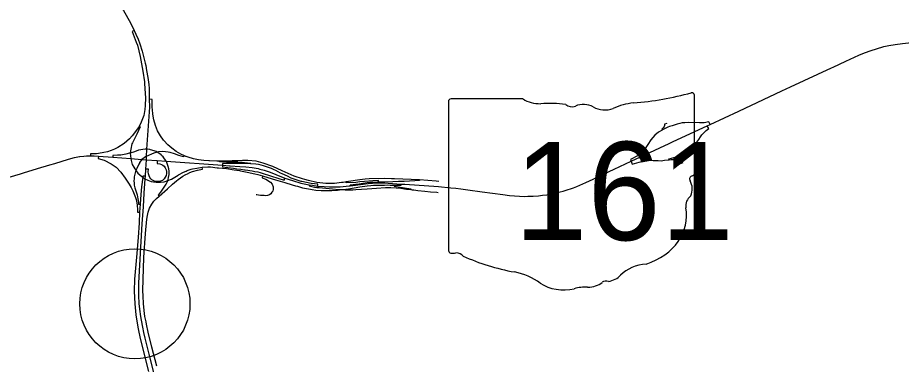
# Model space of a CAD drawing. Extents: x 0 to 34, y 0 to 22.
# Drawn here: x 6.732 to 7.89, y 18.908 to 19.363 of the extents above; entities that cross this region are included whole.
import ezdxf

# ---------------------------------------------------------------- set-up
doc = ezdxf.new("R2010")
doc.units = 0
for name, color, linetype in [('GM_X_Interchange_Ramps', 7, 'Continuous'), ('GM_X_Interstate_Route', 7, 'Continuous'), ('GM_X_State_Route', 7, 'Continuous'), ('GM_X_State_Shield', 7, 'Continuous'), ('SH_Text', 7, 'Continuous')]:
    doc.layers.add(name, color=color, linetype=linetype)

msp = doc.modelspace()

# ---------------------------------------------------------------- linework, layer by layer
at = {"layer": 'GM_X_Interchange_Ramps'}
for points in [[(6.8844, 19.3456), (6.8816, 19.3444), (6.887, 19.3303), (6.8885, 19.3264), (6.8924, 19.3115), (6.8959, 19.2923), (6.8977, 19.2784), (6.8979, 19.2767), (6.8985, 19.269), (6.899, 19.2572), (6.8986, 19.2475), (6.8983, 19.2419), (6.897, 19.2343), (6.8963, 19.2319), (6.8937, 19.2253), (6.8909, 19.22), (6.8876, 19.2152), (6.8818, 19.2074), (6.8784, 19.2038), (6.8747, 19.2005), (6.8711, 19.1977), (6.8629, 19.1921), (6.8585, 19.1901), (6.854, 19.1882), (6.8493, 19.1867), (6.8446, 19.1856), (6.8423, 19.1851), (6.835, 19.1841), (6.8273, 19.1839), (6.8273, 19.1815)], [(7.2835, 19.1476), (7.2801, 19.148), (7.2582, 19.15), (7.2255, 19.151), (7.2215, 19.1511), (7.2119, 19.1515), (7.1923, 19.1511), (7.187, 19.1506), (7.1801, 19.1499), (7.1651, 19.1477), (7.162, 19.1472), (7.1584, 19.1466), (7.1562, 19.1462), (7.1468, 19.1452), (7.1354, 19.1452), (7.1238, 19.1466), (7.1129, 19.1489), (7.1079, 19.1503), (7.1049, 19.1512), (7.0942, 19.1547), (7.0783, 19.1617), (7.066, 19.1673), (7.0536, 19.1718), (7.0474, 19.1734), (7.0441, 19.1742), (7.0335, 19.1751), (7.03, 19.1752), (7.0265, 19.1752), (7.0203, 19.1748), (7.0129, 19.1747), (7.0028, 19.1744), (6.9983, 19.1744), (6.9962, 19.1744), (6.9927, 19.1745), (6.983, 19.175), (6.9824, 19.175), (6.9756, 19.1754), (6.9688, 19.1762), (6.9621, 19.1774), (6.9553, 19.1794), (6.9525, 19.1804), (6.9519, 19.1806), (6.9496, 19.1817), (6.9455, 19.1835), (6.9424, 19.1852), (6.9394, 19.187), (6.9336, 19.1912), (6.9283, 19.1959), (6.9233, 19.2014), (6.9229, 19.2019), (6.9189, 19.2075), (6.9151, 19.2142), (6.9121, 19.2212), (6.91, 19.2284), (6.9088, 19.2358), (6.9087, 19.237), (6.9078, 19.2454), (6.9081, 19.2554), (6.9042, 19.2555)], [(7.5823, 19.2239), (7.5795, 19.2227), (7.5792, 19.2213), (7.5787, 19.2198), (7.578, 19.2185), (7.5769, 19.2171), (7.5759, 19.2161), (7.5764, 19.2151)], [(7.639, 19.2225), (7.6373, 19.2258), (7.6312, 19.2247), (7.6252, 19.2244), (7.6102, 19.2249), (7.6059, 19.2248), (7.6024, 19.2244), (7.5994, 19.2238), (7.5958, 19.2229), (7.5896, 19.2208), (7.5861, 19.2198), (7.5837, 19.2188)], [(6.8909, 19.22), (6.8924, 19.2195), (6.8879, 19.2099), (6.8823, 19.1986), (6.8815, 19.1969), (6.8798, 19.1902), (6.8794, 19.1877), (6.879, 19.185), (6.8798, 19.1779), (6.8803, 19.1754), (6.8819, 19.1701), (6.8839, 19.1664), (6.8851, 19.1642), (6.8864, 19.1625), (6.8871, 19.1615), (6.8892, 19.1588), (6.8942, 19.1542), (6.8955, 19.1534), (6.8984, 19.1514), (6.9022, 19.1494), (6.9068, 19.1478), (6.9098, 19.1474), (6.9132, 19.1469), (6.9167, 19.1468), (6.9188, 19.147), (6.9236, 19.1474), (6.9283, 19.1488), (6.9333, 19.1508), (6.9419, 19.156), (6.9426, 19.1564), (6.949, 19.1599), (6.9523, 19.1614), (6.954, 19.162), (6.9592, 19.1639), (6.9607, 19.1642), (6.9663, 19.1653), (6.9735, 19.1666), (6.9807, 19.1669), (6.9842, 19.1668), (6.9931, 19.1658), (6.9947, 19.1656), (7.0053, 19.1646), (7.0156, 19.1632), (7.0223, 19.1621), (7.0237, 19.1618), (7.0323, 19.1601), (7.0423, 19.1578), (7.0462, 19.1568), (7.0524, 19.1551), (7.0652, 19.1513), (7.0695, 19.15), (7.0816, 19.1463), (7.0915, 19.1433), (7.0956, 19.1421), (7.0983, 19.1414), (7.1051, 19.1396), (7.1154, 19.1375), (7.1177, 19.1372), (7.1224, 19.1365), (7.1293, 19.1359), (7.1304, 19.1359), (7.1364, 19.1357), (7.1417, 19.1358), (7.1435, 19.1358), (7.1507, 19.1363), (7.1561, 19.137), (7.158, 19.1373), (7.1652, 19.1382), (7.1726, 19.1395), (7.1801, 19.1407), (7.1895, 19.1419), (7.1946, 19.1425), (7.1982, 19.1428), (7.2018, 19.1429), (7.2054, 19.1431), (7.2105, 19.1431), (7.2126, 19.1431), (7.2162, 19.1432), (7.2197, 19.1431), (7.2249, 19.143), (7.227, 19.143), (7.2306, 19.1429), (7.2342, 19.1427), (7.2344, 19.1444)], [(7.5837, 19.2188), (7.582, 19.2181), (7.5775, 19.2157), (7.5764, 19.2151), (7.5717, 19.2123), (7.5666, 19.2085), (7.5616, 19.2024), (7.5576, 19.1961), (7.5541, 19.1909), (7.5503, 19.1864), (7.5447, 19.1818), (7.5346, 19.1765), (7.5356, 19.1742)], [(7.5994, 19.1816), (7.6029, 19.1825), (7.6076, 19.1856), (7.6121, 19.1884), (7.6165, 19.1919), (7.6191, 19.1951), (7.6219, 19.1993), (7.6243, 19.2029), (7.6264, 19.2062), (7.6282, 19.2089), (7.631, 19.2117), (7.6339, 19.2145), (7.6373, 19.2172), (7.6354, 19.2208)], [(6.917, 19.1285), (6.916, 19.1297), (6.9172, 19.1312), (6.9191, 19.1338), (6.921, 19.1364), (6.9228, 19.139), (6.9246, 19.1416), (6.9262, 19.1442), (6.9275, 19.1469), (6.9283, 19.1488), (6.9292, 19.1525), (6.9299, 19.1554), (6.93, 19.1564), (6.9301, 19.1584), (6.9301, 19.1613), (6.9297, 19.1643), (6.9291, 19.1672), (6.9282, 19.17), (6.9271, 19.1727), (6.9262, 19.1743), (6.9257, 19.1752), (6.9242, 19.1776), (6.9223, 19.1799), (6.9203, 19.182), (6.9196, 19.1825), (6.918, 19.1839), (6.9145, 19.1862), (6.9131, 19.1869), (6.9104, 19.1881), (6.9058, 19.1893), (6.9048, 19.1896), (6.9018, 19.1899), (6.9007, 19.1899), (6.8989, 19.1899), (6.8959, 19.1897), (6.893, 19.1893), (6.8902, 19.1886), (6.8846, 19.1866), (6.879, 19.185), (6.8781, 19.1847), (6.8734, 19.1835), (6.8668, 19.1824), (6.8623, 19.1821), (6.8566, 19.1819), (6.8565, 19.1796)], [(6.8374, 19.1811), (6.8373, 19.1779), (6.8451, 19.1757), (6.8541, 19.1709), (6.8607, 19.1664), (6.8667, 19.1601), (6.8725, 19.1522), (6.878, 19.1442), (6.8806, 19.1397), (6.8827, 19.1356), (6.8845, 19.1312), (6.886, 19.1268), (6.8869, 19.1243), (6.8872, 19.1219), (6.8881, 19.1173), (6.8884, 19.1147), (6.8885, 19.1123), (6.8887, 19.1075), (6.8915, 19.1075)], [(6.9496, 19.1817), (6.9492, 19.1802), (6.9431, 19.182), (6.9371, 19.1839), (6.9315, 19.1856), (6.9287, 19.1863), (6.9218, 19.1871), (6.9163, 19.1866), (6.9145, 19.1862), (6.9103, 19.185), (6.9069, 19.1837), (6.9032, 19.1819), (6.9002, 19.1806), (6.8994, 19.1802), (6.8973, 19.1786), (6.8945, 19.1764), (6.8915, 19.1724), (6.8912, 19.1719), (6.8905, 19.1703), (6.8895, 19.1681), (6.8873, 19.1643), (6.8867, 19.163), (6.8864, 19.1625), (6.8851, 19.1573), (6.8845, 19.1538), (6.8842, 19.151), (6.884, 19.1487), (6.8842, 19.1455), (6.8844, 19.1427), (6.8853, 19.1394), (6.8881, 19.13), (6.8893, 19.1251), (6.89, 19.1206), (6.8901, 19.1178), (6.8923, 19.1178)], [(7.5855, 19.1763), (7.5852, 19.1773), (7.5886, 19.1781), (7.5979, 19.1811), (7.5994, 19.1816)], [(6.9142, 18.9055), (6.9076, 18.9307), (6.9029, 18.9502), (6.9006, 18.9605), (6.8999, 18.9638), (6.8985, 18.9707), (6.8974, 18.9786), (6.8964, 18.9878), (6.896, 18.9973), (6.8956, 19.0046), (6.8972, 19.0481), (6.8993, 19.0797), (6.9011, 19.0984), (6.9019, 19.1033), (6.9028, 19.1073), (6.9046, 19.1126), (6.9074, 19.1178), (6.9103, 19.1217), (6.9138, 19.1255), (6.917, 19.1285), (6.9281, 19.1382), (6.9348, 19.1441), (6.9397, 19.1485), (6.9419, 19.1502), (6.945, 19.1526), (6.948, 19.1546), (6.951, 19.1563), (6.952, 19.1568), (6.9541, 19.1578), (6.9573, 19.1593), (6.9606, 19.1606), (6.9672, 19.1626), (6.9717, 19.1634), (6.974, 19.1639), (6.9735, 19.1666)], [(6.9147, 19.1752), (6.9145, 19.1714), (6.9178, 19.1707), (6.92, 19.17), (6.9218, 19.169), (6.9236, 19.1676), (6.925, 19.1657), (6.9263, 19.163), (6.9267, 19.1609), (6.9268, 19.1584), (6.9262, 19.1557), (6.9251, 19.1534), (6.9236, 19.1511), (6.9213, 19.1491), (6.9187, 19.148), (6.9171, 19.1476), (6.9146, 19.1475), (6.912, 19.1479), (6.91, 19.1486), (6.9077, 19.15), (6.9063, 19.1514), (6.9049, 19.153), (6.9038, 19.1552), (6.903, 19.1577), (6.9029, 19.1602), (6.9032, 19.1639), (6.8992, 19.164)], [(7.037, 19.1708), (7.0371, 19.1713), (7.0288, 19.1721), (7.0257, 19.1724), (7.0227, 19.1727), (7.0203, 19.1729), (7.0132, 19.1729), (7.0105, 19.173), (7.0079, 19.173), (7.0052, 19.1731), (6.9963, 19.1735), (6.9962, 19.1744)], [(7.0001, 19.169), (7, 19.1669), (7.0036, 19.1665), (7.007, 19.1661), (7.0147, 19.1651), (7.0187, 19.1645), (7.024, 19.1637), (7.029, 19.1631), (7.0299, 19.163), (7.0335, 19.1625), (7.0358, 19.1621), (7.0392, 19.1617), (7.0427, 19.161), (7.0464, 19.1602)], [(7.0472, 19.1701), (7.0439, 19.1703), (7.037, 19.1708), (7.0316, 19.1711), (7.0261, 19.1713), (7.0193, 19.1712), (7.0003, 19.1714), (7.0001, 19.169)], [(7.1246, 19.1417), (7.1249, 19.1441), (7.1164, 19.1452), (7.1042, 19.1475), (7.1031, 19.1477), (7.0952, 19.1502), (7.0901, 19.1522), (7.0851, 19.1545), (7.0785, 19.1577), (7.0761, 19.1588), (7.0699, 19.1621), (7.0677, 19.1631), (7.0642, 19.1646), (7.054, 19.1682), (7.0508, 19.1691), (7.0472, 19.1701)], [(7.5356, 19.1742), (7.5371, 19.1704), (7.546, 19.1731), (7.5535, 19.1748), (7.5591, 19.1757), (7.5647, 19.1752), (7.5711, 19.1751), (7.5752, 19.175), (7.5793, 19.1756), (7.5855, 19.1763), (7.588, 19.1767), (7.5908, 19.1764), (7.5936, 19.1755), (7.5959, 19.1745), (7.5978, 19.1735), (7.5992, 19.1724), (7.6002, 19.1714), (7.6036, 19.1727)], [(6.8986, 19.1546), (6.8957, 19.1549), (6.8955, 19.1534), (6.8938, 19.1409), (6.8931, 19.1308), (6.8923, 19.1178), (6.8915, 19.1075), (6.8907, 19.0934), (6.8895, 19.0743), (6.8873, 19.0485), (6.8859, 19.0339), (6.885, 19.0195), (6.8842, 19.0039), (6.8853, 18.9873), (6.8865, 18.973), (6.8882, 18.962), (6.8898, 18.9544), (6.8923, 18.9419), (6.9032, 18.8985)], [(7.0524, 19.1551), (7.0521, 19.1527), (7.057, 19.1506), (7.0631, 19.1467), (7.0653, 19.1441), (7.0667, 19.1405), (7.0667, 19.1378), (7.0661, 19.1351), (7.0649, 19.1337), (7.0635, 19.1316), (7.0615, 19.1304), (7.0592, 19.1295), (7.057, 19.1291), (7.0547, 19.1292), (7.0522, 19.1293), (7.05, 19.1295), (7.0473, 19.1299), (7.0452, 19.1303), (7.0444, 19.1304)], [(7.0464, 19.1602), (7.0495, 19.1597), (7.0657, 19.1542), (7.0714, 19.1524), (7.0752, 19.1512), (7.0783, 19.1503), (7.081, 19.1495), (7.0817, 19.1522)], [(7.1139, 19.1434), (7.1136, 19.1419), (7.1208, 19.1404), (7.1237, 19.14), (7.1267, 19.1397), (7.1441, 19.138), (7.1527, 19.1372), (7.1561, 19.137), (7.1609, 19.1367), (7.1649, 19.1366), (7.1707, 19.1367), (7.1748, 19.1371), (7.1897, 19.1381), (7.2018, 19.139), (7.2137, 19.1397), (7.2208, 19.1397), (7.2276, 19.1393), (7.2338, 19.1388), (7.2414, 19.1377), (7.2468, 19.1371), (7.2488, 19.1369), (7.2509, 19.1366), (7.2562, 19.136), (7.2652, 19.135), (7.2729, 19.1343), (7.281, 19.1336), (7.2828, 19.1334)], [(7.2042, 19.1458), (7.2042, 19.1468), (7.2044, 19.1492), (7.197, 19.1487), (7.1864, 19.1478), (7.1802, 19.1471), (7.1747, 19.1465), (7.1621, 19.1458), (7.162, 19.1472)], [(7.2582, 19.15), (7.2581, 19.1492), (7.2521, 19.1487), (7.2452, 19.1483), (7.2381, 19.1479), (7.2308, 19.1475), (7.2234, 19.1472), (7.2127, 19.147), (7.2042, 19.1468), (7.1985, 19.1466), (7.1926, 19.1462), (7.1842, 19.1452), (7.179, 19.1444), (7.1747, 19.1437), (7.1676, 19.1427), (7.1676, 19.1421)], [(7.2249, 19.143), (7.2249, 19.1417), (7.2302, 19.1408), (7.2362, 19.1398), (7.2469, 19.138), (7.2468, 19.1371)]]:
    msp.add_lwpolyline(points, dxfattribs=at)
at = {"layer": 'GM_X_Interstate_Route'}
for points in [[(6.8183, 19.4291), (6.8195, 19.4283), (6.8298, 19.4197), (6.8389, 19.4116), (6.8482, 19.4021), (6.8568, 19.3914), (6.8705, 19.3717), (6.8797, 19.3559), (6.8844, 19.3456), (6.8865, 19.341), (6.8894, 19.3341), (6.8916, 19.328), (6.8947, 19.3185), (6.8966, 19.3117), (6.8988, 19.303), (6.8995, 19.2998), (6.9007, 19.2933), (6.9024, 19.2841), (6.9034, 19.275), (6.9039, 19.2696), (6.9042, 19.2555)], [(6.9042, 19.2555), (6.9043, 19.2453), (6.9007, 19.1899), (6.9002, 19.1806), (6.9002, 19.18)], [(6.9002, 19.1777), (6.9001, 19.1762), (6.8992, 19.164)], [(6.9002, 19.18), (6.9002, 19.1777)], [(6.8986, 19.1546), (6.8984, 19.1514), (6.8972, 19.1324), (6.896, 19.1146), (6.8946, 19.0924), (6.89, 19.0149), (6.8899, 18.9985), (6.8899, 18.9981)], [(6.8992, 19.164), (6.8986, 19.1546)], [(6.8899, 18.9981), (6.8906, 18.9878), (6.8912, 18.9803), (6.8926, 18.9706), (6.8947, 18.9588), (6.8951, 18.9569)], [(6.8951, 18.9569), (6.8966, 18.9496), (6.8982, 18.9425)], [(6.8982, 18.9425), (6.8983, 18.9422), (6.9034, 18.9214), (6.9095, 18.8974)]]:
    msp.add_lwpolyline(points, dxfattribs=at)
at = {"layer": 'GM_X_State_Route'}
for points in [[(7.8002, 19.2975), (7.8172, 19.3055), (7.8341, 19.3134), (7.8413, 19.3165), (7.85, 19.3196), (7.8571, 19.3218), (7.8668, 19.3245), (7.8732, 19.326), (7.8816, 19.3275), (7.8911, 19.3288), (7.8993, 19.3295), (7.9089, 19.3298), (7.9227, 19.3292), (7.9466, 19.3276), (7.9507, 19.3273), (7.989, 19.3249), (8.0294, 19.3225), (8.0354, 19.3221), (8.0839, 19.3189)], [(7.5854, 19.1977), (7.5909, 19.2003), (7.6354, 19.2208), (7.639, 19.2225), (7.6766, 19.24), (7.7331, 19.2665), (7.7443, 19.2716), (7.7805, 19.2885), (7.7983, 19.2966), (7.8002, 19.2975)], [(7.5356, 19.1742), (7.5854, 19.1977)], [(6.7737, 19.1694), (6.7806, 19.1714), (6.7984, 19.1771), (6.806, 19.179), (6.8129, 19.1805)], [(6.8129, 19.1805), (6.813, 19.1805), (6.8185, 19.1811), (6.8218, 19.1814), (6.8252, 19.1815), (6.8273, 19.1815), (6.832, 19.1812), (6.8374, 19.1811), (6.8565, 19.1796), (6.8798, 19.1779), (6.8894, 19.1769)], [(6.7577, 19.1646), (6.7737, 19.1694)], [(6.8894, 19.1769), (6.8945, 19.1764), (6.9001, 19.1762), (6.9147, 19.1752), (6.9262, 19.1743), (7.0001, 19.169), (7.0091, 19.1683), (7.0103, 19.1682), (7.0227, 19.1673), (7.0306, 19.1668), (7.039, 19.166), (7.0468, 19.1647), (7.0492, 19.164)], [(7.425, 19.1304), (7.4286, 19.131), (7.4344, 19.1321), (7.4387, 19.1331), (7.4466, 19.1352), (7.4532, 19.1372), (7.4561, 19.1382), (7.4602, 19.1396), (7.4643, 19.1412), (7.4684, 19.143), (7.4764, 19.1466), (7.4859, 19.1509), (7.4994, 19.1574), (7.5136, 19.1639), (7.5356, 19.1742)], [(6.6936, 19.1454), (6.7354, 19.1579), (6.7394, 19.1591)], [(6.7394, 19.1591), (6.7577, 19.1646)], [(7.0492, 19.164), (7.0545, 19.1625), (7.0587, 19.1611), (7.0626, 19.1598), (7.0702, 19.1567), (7.0817, 19.1522), (7.0918, 19.1488), (7.1026, 19.1457), (7.1139, 19.1434)], [(7.1139, 19.1434), (7.1179, 19.1427), (7.1246, 19.1417), (7.1257, 19.1415), (7.1335, 19.1412), (7.1402, 19.1407), (7.1541, 19.1409), (7.1663, 19.1419), (7.1676, 19.1421), (7.1745, 19.143), (7.1841, 19.1442), (7.1846, 19.1443)], [(7.1846, 19.1443), (7.1908, 19.145), (7.1968, 19.1455), (7.2029, 19.1458), (7.2042, 19.1458), (7.2104, 19.1459), (7.217, 19.1457), (7.2344, 19.1444)], [(7.2344, 19.1444), (7.2391, 19.144), (7.2832, 19.1412), (7.2994, 19.1395), (7.306, 19.1388), (7.3123, 19.1381), (7.3218, 19.1369), (7.3402, 19.1343), (7.3673, 19.1306), (7.3762, 19.1294), (7.3829, 19.1288), (7.3895, 19.1284), (7.3958, 19.1282), (7.4002, 19.1283)], [(7.4002, 19.1283), (7.4007, 19.1283), (7.4071, 19.1285), (7.4141, 19.1291), (7.4194, 19.1296), (7.425, 19.1304)]]:
    msp.add_lwpolyline(points, dxfattribs=at)
at = {"layer": 'GM_X_State_Shield'}
for p, q in [((7.6185, 19.1585), (7.6185, 19.2608)), ((7.2964, 19.2526), (7.2964, 19.057)), ((7.3939, 19.256), (7.2996, 19.256)), ((7.6185, 19.1585), (7.6185, 19.1585))]:
    msp.add_line(p, q, dxfattribs=at)
for centre, major_axis, start_param, end_param in [((7.5038, 19.5226), (0.3416, 0), 4.814394, 5.042369), ((7.615, 19.2612), (0.00359, 0), 6.141152, 7.989035), ((7.3001, 19.253), (0.00373, 0), 1.712693, 3.28349), ((7.4164, 19.2787), (0.0362, 0), 4.042523, 4.731795), ((7.4284, 19.1462), (0.1299, 0), 1.404758, 1.657858), ((7.4579, 19.254), (0.0104, 0), 3.836095, 5.185415), ((7.4732, 19.2314), (0.0217, 0), 0.950623, 2.079405), ((7.5474, 19.1962), (0.0687, 0), 1.699011, 2.107814), ((7.5013, 19.2624), (0.0261, 0), 4.081561, 5.145723), ((7.6177, 19.151), (0.00555, 0), 1.883978, 3.671073), ((7.6147, 19.1581), (0.00384, 0), 5.05454, 6.418171), ((7.5824, 19.1381), (0.0333, 0), 5.934695, 6.695948), ((7.6314, 19.1157), (0.0242, 0), 2.387724, 3.262537), ((7.5229, 19.1027), (0.0854, 0), 5.101752, 6.440018), ((7.3002, 19.0566), (0.00376, 0), 3.00124, 4.508301), ((7.3007, 19.0766), (0.0287, 0), 4.665946, 4.897461), ((7.3066, 19.0457), (0.0104, 0), 0.519207, 1.627899), ((7.4374, 19.2215), (0.2467, 0), 4.195997, 4.488961), ((7.559, 19.0021), (0.0468, 0), 1.647645, 2.488434), ((7.3639, 18.9692), (0.0772, 0), 0.823519, 1.323587), ((7.4792, 19.0301), (0.0261, 0), 4.691044, 5.507374), ((7.5028, 19.0112), (0.00735, 0), 1.147584, 2.315152), ((7.4997, 19.0381), (0.0276, 0), 4.937069, 5.64225), ((7.4473, 19.0448), (0.049, 0), 4.026481, 4.996735), ((7.4756, 18.9771), (0.0402, 0), 1.495662, 1.94098)]:
    msp.add_ellipse(centre, major_axis=major_axis, ratio=0.8, start_param=start_param, end_param=end_param, dxfattribs=at)
at = {"layer": 'SH_Text'}
msp.add_circle((6.8853, 18.9873), 0.0722, dxfattribs=at)

# ---------------------------------------------------------------- texts
at = {"layer": 'GM_X_State_Shield'}
msp.add_text('161', height=0.12885, dxfattribs=at).set_placement((7.3826, 19.0708))

doc.saveas('drawing.dxf')
